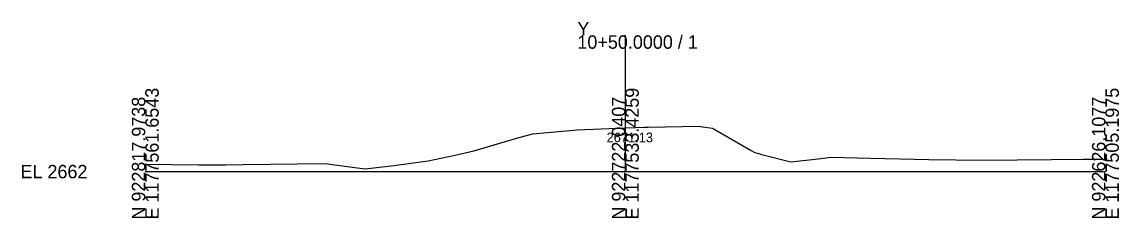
# Model space of a CAD drawing. Extents: x -26 to 203, y -10 to 2034.
# Drawn here: x -25.7 to 202.8, y 490.3 to 531.2 of the extents above; entities that cross this region are included whole.
import ezdxf

# ---------------------------------------------------------------- set-up
doc = ezdxf.new("R2010")
doc.units = 0
for name, color, linetype in [('Exist Cross Section Cell', 7, 'Continuous'), ('Exist XS Center Line Elevation Label', 7, 'Continuous'), ('Exist XS Ground Line', 7, 'Continuous')]:
    doc.layers.add(name, color=color, linetype=linetype)

msp = doc.modelspace()

# ---------------------------------------------------------------- linework, layer by layer
at = {"layer": 'Exist Cross Section Cell'}
for p, q in [((100, 500), (100, 528.42)), ((0, 500), (100, 500)), ((100, 500), (200, 500))]:
    msp.add_line(p, q, dxfattribs=at)
at = {"layer": 'Exist XS Ground Line'}
for p, q in [((78.08, 507.16), (80.7, 507.86)), ((80.7, 507.86), (88.43, 508.6)), ((88.43, 508.6), (89.89, 508.74)), ((89.89, 508.74), (100, 509.13)), ((100, 509.13), (102.17, 509.21)), ((102.17, 509.21), (103.85, 509.29)), ((103.85, 509.29), (104.78, 509.3)), ((104.78, 509.3), (115.4, 509.47)), ((115.4, 509.47), (116.07, 509.37)), ((116.07, 509.37), (118.15, 509.03)), ((118.15, 509.03), (126.21, 504.43)), ((68.44, 504.32), (78.08, 507.16)), ((58.93, 502.22), (64.17, 503.33)), ((64.17, 503.33), (68.44, 504.32)), ((126.21, 504.43), (126.99, 503.98)), ((126.99, 503.98), (127.81, 503.76)), ((127.81, 503.76), (128.17, 503.67)), ((128.17, 503.67), (134.48, 502.06)), ((140.15, 502.67), (142.82, 502.98)), ((142.82, 502.98), (151.04, 502.78)), ((151.04, 502.78), (163.22, 502.54)), ((0, 501.52), (11.15, 501.41)), ((11.15, 501.41), (16.71, 501.44)), ((16.71, 501.44), (20.4, 501.48)), ((20.4, 501.48), (37.48, 501.71)), ((37.48, 501.71), (38.98, 501.5)), ((38.98, 501.5), (45.74, 500.61)), ((45.74, 500.61), (46.36, 500.67)), ((46.36, 500.67), (51.81, 501.29)), ((51.81, 501.29), (54.81, 501.72)), ((54.81, 501.72), (58.93, 502.22)), ((134.48, 502.06), (140.15, 502.67)), ((163.22, 502.54), (174.44, 502.41)), ((174.44, 502.41), (188.78, 502.55)), ((188.78, 502.55), (195.35, 502.61)), ((195.35, 502.61), (200, 502.56))]:
    msp.add_line(p, q, dxfattribs=at)

# ---------------------------------------------------------------- texts
at = {"layer": 'Exist Cross Section Cell'}
for s, p in [('Y', (90, 528.42)), ('10+50.0000 / 1', (90, 525.62)), ('EL 2662', (-26, 498.6))]:
    msp.add_text(s, height=2.8, dxfattribs=at).set_placement(p)
for s, p in [('E 1177561.6543', (2.8, 490)), ('E 1177533.4259', (102.8, 490)), ('E 1177505.1975', (202.8, 490)), ('N 922817.9738', (0, 490)), ('N 922722.0407', (100, 490)), ('N 922626.1077', (200, 490))]:
    msp.add_text(s, height=2.8, rotation=90, dxfattribs=at).set_placement(p)
at = {"layer": 'Exist XS Center Line Elevation Label'}
msp.add_text('2671.13', height=2, dxfattribs=at).set_placement((96.09, 506.13))

doc.saveas('drawing.dxf')
